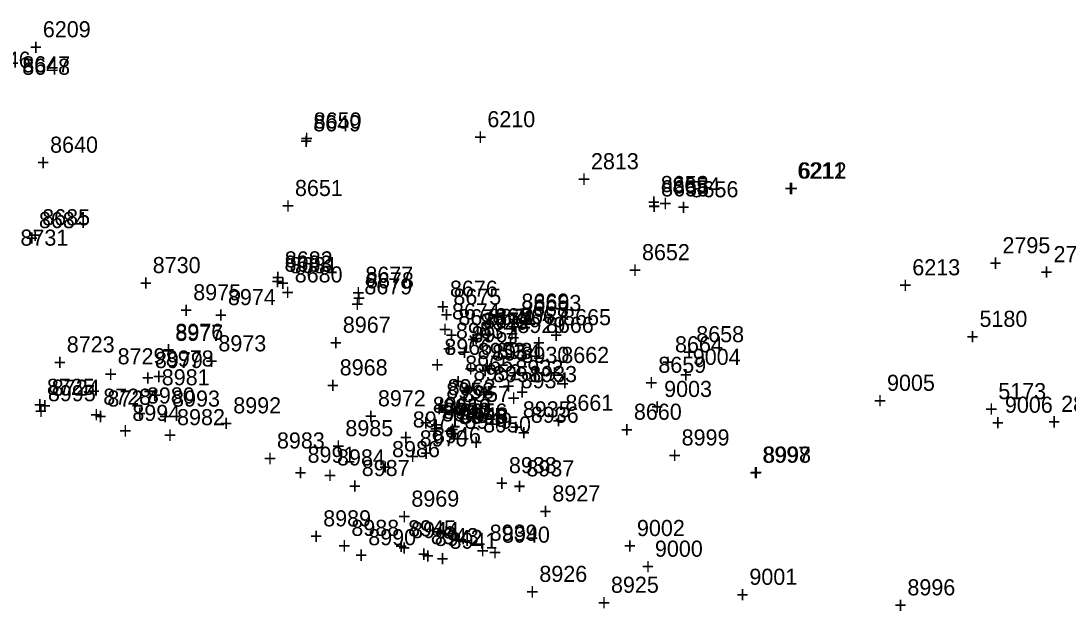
# Model space of a CAD drawing. Extents: x 1136220 to 1137808, y 528804 to 531215.
# Drawn here: x 1136624.6 to 1136787.3, y 529546.8 to 529638.4 of the extents above; entities that cross this region are included whole.
import ezdxf

# ---------------------------------------------------------------- set-up
doc = ezdxf.new("R2010")
doc.units = 0
for name, color, linetype in [('S_Buildings', 7, 'Continuous'), ('S_Buildings_Steps_Brick', 7, 'Continuous'), ('S_Curb_Type_3', 7, 'Continuous'), ('S_Drainage_Culvert_Top', 7, 'Continuous'), ('S_Fencing_BarbedWire', 7, 'Continuous'), ('S_Ground_Elevation', 7, 'Continuous'), ('S_Ground_LevelString', 7, 'Continuous'), ('S_Property_Garden', 7, 'Continuous'), ('S_Property_Walkways', 7, 'Continuous'), ('S_Roadway_Centerline', 7, 'Continuous'), ('S_Roadway_Drive_Gravel', 7, 'Continuous'), ('S_Roadway_Edge_Pavement', 7, 'Continuous'), ('S_Trees_Bush', 7, 'Continuous'), ('S_Trees_Bush_Line', 7, 'Continuous'), ('S_Trees_Conifer_NonPay', 7, 'Continuous'), ('S_Utilities_Gas_Gate', 7, 'Continuous'), ('S_Utilities_Pole_Joint', 7, 'Continuous'), ('S_Utilities_UG_Gas_Line', 7, 'Continuous'), ('S_Utilities_UG_Sanitary_MH', 7, 'Continuous')]:
    doc.layers.add(name, color=color, linetype=linetype)

msp = doc.modelspace()

# ---------------------------------------------------------------- texts
at = {"layer": 'S_Buildings'}
for s, p in [('8725', (1136628.65, 529580.36)), ('+', (1136626.59, 529577.61)), ('8991', (1136669.16, 529569.82)), ('+', (1136667.1, 529567.07))]:
    msp.add_text(s, height=2.5, dxfattribs=at).set_placement(p)
at = {"layer": 'S_Buildings_Steps_Brick'}
for s, p in [('8963', (1136692.21, 529589.07)), ('8964', (1136694.63, 529588.51)), ('+', (1136690.15, 529586.32)), ('+', (1136692.57, 529585.76)), ('8965', (1136693.66, 529583.96)), ('+', (1136691.6, 529581.21)), ('8958', (1136690.71, 529579.77)), ('8962', (1136690.94, 529580.31)), ('8957', (1136693.18, 529579.26)), ('+', (1136688.65, 529577.02)), ('+', (1136688.88, 529577.56)), ('8960', (1136690.17, 529576.63)), ('8959', (1136690.23, 529577.23)), ('+', (1136691.12, 529576.51)), ('8955', (1136692.61, 529575.84)), ('8956', (1136692.76, 529576.52)), ('+', (1136688.17, 529574.48)), ('+', (1136688.11, 529573.88)), ('+', (1136690.55, 529573.09)), ('+', (1136690.7, 529573.77))]:
    msp.add_text(s, height=2.5, dxfattribs=at).set_placement(p)
at = {"layer": 'S_Curb_Type_3'}
for s, p in [('8646', (1136618.69, 529631.15)), ('8647', (1136624.82, 529630.43)), ('8650', (1136670.11, 529621.71)), ('+', (1136668.04, 529618.96)), ('8653', (1136724.05, 529611.84)), ('8654', (1136725.84, 529611.61)), ('+', (1136721.99, 529609.09)), ('+', (1136723.78, 529608.86)), ('2795', (1136777.15, 529602.34)), ('2796', (1136785.08, 529600.96)), ('+', (1136775.08, 529599.59)), ('+', (1136783.02, 529598.21))]:
    msp.add_text(s, height=2.5, dxfattribs=at).set_placement(p)
at = {"layer": 'S_Drainage_Culvert_Top'}
for s, p in [('2806', (1136786.27, 529577.72)), ('+', (1136784.21, 529574.97))]:
    msp.add_text(s, height=2.5, dxfattribs=at).set_placement(p)
at = {"layer": 'S_Fencing_BarbedWire'}
for s, p in [('8995', (1136628.81, 529579.37)), ('+', (1136626.75, 529576.62)), ('8994', (1136641.93, 529576.31)), ('+', (1136639.87, 529573.56))]:
    msp.add_text(s, height=2.5, dxfattribs=at).set_placement(p)
at = {"layer": 'S_Ground_Elevation'}
for s, p in [('8684', (1136627.41, 529606.24)), ('8731', (1136624.54, 529603.52)), ('+', (1136625.35, 529603.49)), ('8730', (1136645.1, 529599.26)), ('8683', (1136665.57, 529599.48)), ('+', (1136643.04, 529596.51)), ('+', (1136663.51, 529596.73)), ('8975', (1136651.39, 529595.04)), ('8974', (1136656.78, 529594.29)), ('+', (1136649.33, 529592.29)), ('+', (1136654.72, 529591.54)), ('8928', (1136695.99, 529590.48)), ('8977', (1136648.61, 529588.74)), ('8976', (1136648.62, 529588.9)), ('8967', (1136674.64, 529590)), ('8929', (1136701.77, 529589.96)), ('8973', (1136655.3, 529587.11)), ('+', (1136693.93, 529587.73)), ('8723', (1136631.74, 529586.94)), ('+', (1136646.56, 529586.15)), ('+', (1136646.55, 529585.99)), ('+', (1136672.58, 529587.25)), ('8966', (1136690.42, 529586.56)), ('8953', (1136695.6, 529585.93)), ('8954', (1136697.83, 529585.67)), ('8931', (1136698.54, 529585.93)), ('+', (1136699.71, 529587.21)), ('8729', (1136639.64, 529585.1)), ('8979', (1136645.44, 529584.52)), ('8978', (1136647.13, 529584.76)), ('+', (1136653.24, 529584.36)), ('8930', (1136702.4, 529585.33)), ('9004', (1136729.02, 529585.01)), ('+', (1136629.68, 529584.19)), ('8968', (1136674.16, 529583.38)), ('+', (1136688.36, 529583.81)), ('+', (1136693.54, 529583.18)), ('8952', (1136694.94, 529582.6)), ('+', (1136695.77, 529582.92)), ('+', (1136696.48, 529583.18)), ('8951', (1136697.98, 529582.34)), ('+', (1136700.34, 529582.58)), ('8932', (1136701.46, 529583.27)), ('8933', (1136703.6, 529582.34)), ('+', (1136637.58, 529582.35)), ('+', (1136643.37, 529581.77)), ('+', (1136645.07, 529582.01)), ('8981', (1136646.5, 529581.84)), ('8934', (1136702.27, 529581.38)), ('+', (1136726.96, 529582.26)), ('9005', (1136759.21, 529580.99)), ('8724', (1136629.4, 529580.22)), ('8980', (1136644.19, 529579.02)), ('+', (1136672.1, 529580.63)), ('+', (1136692.88, 529579.85)), ('+', (1136695.92, 529579.59)), ('+', (1136699.4, 529580.52)), ('+', (1136701.54, 529579.59)), ('9003', (1136724.57, 529580.03)), ('8727', (1136638.06, 529578.54)), ('+', (1136644.44, 529579.09)), ('8972', (1136680.09, 529578.58)), ('8961', (1136688.62, 529577.55)), ('+', (1136700.21, 529578.63)), ('+', (1136757.15, 529578.24)), ('9006', (1136777.53, 529577.58)), ('+', (1136627.34, 529577.47)), ('+', (1136642.13, 529576.27)), ('8982', (1136648.88, 529575.65)), ('8935', (1136702.61, 529576.86)), ('8936', (1136703.86, 529576.03)), ('+', (1136722.51, 529577.28)), ('+', (1136636, 529575.79)), ('+', (1136678.03, 529575.83)), ('8971', (1136685.51, 529575.29)), ('+', (1136686.56, 529574.8)), ('8949', (1136693.54, 529575.1)), ('8950', (1136696.44, 529574.52)), ('+', (1136775.47, 529574.83)), ('+', (1136646.81, 529572.9)), ('8985', (1136675.03, 529573.94)), ('8946', (1136688.66, 529572.85)), ('+', (1136700.55, 529574.11)), ('+', (1136701.8, 529573.28)), ('8999', (1136727.29, 529572.5)), ('8983', (1136664.4, 529572.03)), ('+', (1136672.97, 529571.19)), ('+', (1136683.45, 529572.54)), ('8970', (1136686.59, 529572.35)), ('+', (1136691.47, 529572.35)), ('+', (1136694.38, 529571.77)), ('8984', (1136673.73, 529569.4)), ('8986', (1136682.29, 529570.69)), ('+', (1136684.52, 529569.6)), ('+', (1136686.6, 529570.1)), ('+', (1136725.23, 529569.75)), ('8997', (1136739.85, 529569.82)), ('8998', (1136739.96, 529569.83)), ('+', (1136662.34, 529569.28)), ('8987', (1136677.58, 529567.75)), ('+', (1136680.23, 529567.94)), ('8938', (1136700.45, 529568.2)), ('8937', (1136703.17, 529567.7)), ('+', (1136671.67, 529566.65)), ('+', (1136737.79, 529567.07)), ('+', (1136737.9, 529567.08)), ('+', (1136675.52, 529565)), ('+', (1136698.39, 529565.45)), ('+', (1136701.11, 529564.95)), ('8969', (1136685.29, 529563)), ('+', (1136683.23, 529560.25)), ('8988', (1136675.96, 529558.46)), ('8945', (1136684.79, 529558.39)), ('9002', (1136720.35, 529558.44)), ('8990', (1136678.59, 529557.01)), ('8942', (1136688.93, 529556.9)), ('8941', (1136691.22, 529556.47)), ('8939', (1136697.46, 529557.71)), ('8940', (1136699.38, 529557.41)), ('+', (1136673.9, 529555.71)), ('+', (1136682.72, 529555.64)), ('+', (1136695.39, 529554.96)), ('+', (1136718.28, 529555.69)), ('9000', (1136723.14, 529555.23)), ('+', (1136676.53, 529554.26)), ('+', (1136686.87, 529554.15)), ('+', (1136689.16, 529553.72)), ('+', (1136697.32, 529554.66)), ('+', (1136721.08, 529552.48)), ('9001', (1136737.82, 529550.87)), ('+', (1136735.76, 529548.12))]:
    msp.add_text(s, height=2.5, dxfattribs=at).set_placement(p)
at = {"layer": 'S_Ground_LevelString'}
for s, p in [('8678', (1136678.24, 529596.9)), ('+', (1136676.18, 529594.15)), ('8675', (1136691.82, 529594.35)), ('8668', (1136702.33, 529592.48)), ('+', (1136689.76, 529591.6)), ('8665', (1136708.88, 529591.17)), ('+', (1136700.27, 529589.73)), ('+', (1136706.82, 529588.42)), ('8664', (1136726.26, 529586.96)), ('+', (1136724.2, 529584.21))]:
    msp.add_text(s, height=2.5, dxfattribs=at).set_placement(p)
at = {"layer": 'S_Property_Garden'}
for s, p in [('8989', (1136671.59, 529559.94)), ('+', (1136669.53, 529557.19))]:
    msp.add_text(s, height=2.5, dxfattribs=at).set_placement(p)
at = {"layer": 'S_Property_Walkways'}
for s, p in [('8947', (1136690.01, 529576.24)), ('8948', (1136692.92, 529575.91)), ('+', (1136687.95, 529573.49)), ('+', (1136690.85, 529573.16)), ('8944', (1136685.25, 529558.13)), ('8943', (1136688.32, 529557.17)), ('+', (1136683.19, 529555.38)), ('+', (1136686.26, 529554.42))]:
    msp.add_text(s, height=2.5, dxfattribs=at).set_placement(p)
at = {"layer": 'S_Roadway_Centerline'}
for s, p in [('8640', (1136629.15, 529617.95)), ('+', (1136627.09, 529615.2)), ('8651', (1136667.2, 529611.23)), ('+', (1136665.14, 529608.48)), ('8652', (1136721.13, 529601.26)), ('+', (1136719.06, 529598.51)), ('5180', (1136773.58, 529590.92)), ('+', (1136771.51, 529588.17))]:
    msp.add_text(s, height=2.5, dxfattribs=at).set_placement(p)
at = {"layer": 'S_Roadway_Drive_Gravel'}
for s, p in [('8663', (1136704.27, 529593.38)), ('+', (1136702.21, 529590.63)), ('8662', (1136708.59, 529585.3)), ('8659', (1136723.67, 529583.78)), ('+', (1136706.53, 529582.55)), ('+', (1136721.61, 529581.03)), ('8661', (1136709.23, 529577.88)), ('8660', (1136719.87, 529576.49)), ('+', (1136707.17, 529575.13)), ('+', (1136717.81, 529573.74)), ('8927', (1136707.21, 529563.81)), ('+', (1136705.15, 529561.06)), ('8926', (1136705.18, 529551.32)), ('8925', (1136716.31, 529549.63)), ('+', (1136703.12, 529548.57)), ('+', (1136714.25, 529546.88))]:
    msp.add_text(s, height=2.5, dxfattribs=at).set_placement(p)
at = {"layer": 'S_Roadway_Edge_Pavement'}
for s, p in [('8648', (1136624.82, 529630.05)), ('8649', (1136670.04, 529621.27)), ('+', (1136667.98, 529618.52)), ('8655', (1136724.11, 529611.17)), ('8656', (1136728.68, 529611.03)), ('8685', (1136627.92, 529606.68)), ('+', (1136722.05, 529608.42)), ('+', (1136726.62, 529608.28)), ('+', (1136625.86, 529603.93)), ('8682', (1136665.62, 529600.14)), ('8681', (1136666.4, 529599.24)), ('+', (1136663.56, 529597.39)), ('8680', (1136667.16, 529597.81)), ('8677', (1136678.14, 529597.76)), ('+', (1136664.34, 529596.49)), ('8679', (1136677.99, 529595.96)), ('8676', (1136691.28, 529595.59)), ('+', (1136665.1, 529595.06)), ('+', (1136676.08, 529595.01)), ('8669', (1136702.4, 529593.59)), ('+', (1136675.92, 529593.21)), ('+', (1136689.22, 529592.84)), ('8674', (1136691.6, 529592.07)), ('8673', (1136692.6, 529591.16)), ('8672', (1136696.44, 529590.66)), ('8671', (1136697.22, 529591.22)), ('8670', (1136698.32, 529591.31)), ('+', (1136700.34, 529590.84)), ('8667', (1136702.02, 529591.38)), ('+', (1136689.54, 529589.32)), ('8666', (1136706.2, 529589.98)), ('+', (1136690.54, 529588.41)), ('+', (1136694.38, 529587.91)), ('+', (1136695.15, 529588.47)), ('+', (1136696.26, 529588.56)), ('+', (1136699.95, 529588.63)), ('8658', (1136729.56, 529588.53)), ('+', (1136704.14, 529587.23)), ('+', (1136727.5, 529585.78)), ('5173', (1136776.5, 529579.69)), ('+', (1136774.44, 529576.94))]:
    msp.add_text(s, height=2.5, dxfattribs=at).set_placement(p)
at = {"layer": 'S_Trees_Bush'}
for s, p in [('8728', (1136637.41, 529578.82)), ('8992', (1136657.61, 529577.48)), ('+', (1136635.35, 529576.07)), ('+', (1136655.55, 529574.73))]:
    msp.add_text(s, height=2.5, dxfattribs=at).set_placement(p)
at = {"layer": 'S_Trees_Bush_Line'}
for s, p in [('8996', (1136762.38, 529549.23)), ('+', (1136760.32, 529546.48))]:
    msp.add_text(s, height=2.5, dxfattribs=at).set_placement(p)
at = {"layer": 'S_Trees_Conifer_NonPay'}
for s, p in [('8993', (1136648.11, 529578.53)), ('+', (1136646.05, 529575.78))]:
    msp.add_text(s, height=2.5, dxfattribs=at).set_placement(p)
at = {"layer": 'S_Utilities_Gas_Gate'}
for s, p in [('6212', (1136745.48, 529613.94)), ('+', (1136743.42, 529611.19))]:
    msp.add_text(s, height=2.5, dxfattribs=at).set_placement(p)
at = {"layer": 'S_Utilities_Pole_Joint'}
for s, p in [('2813', (1136713.2, 529615.38)), ('+', (1136711.14, 529612.63))]:
    msp.add_text(s, height=2.5, dxfattribs=at).set_placement(p)
at = {"layer": 'S_Utilities_UG_Gas_Line'}
for s, p in [('6209', (1136628.02, 529635.87)), ('+', (1136625.96, 529633.12)), ('6210', (1136697.1, 529621.91)), ('+', (1136695.04, 529619.16)), ('6211', (1136745.28, 529613.94)), ('+', (1136743.22, 529611.19))]:
    msp.add_text(s, height=2.5, dxfattribs=at).set_placement(p)
at = {"layer": 'S_Utilities_UG_Sanitary_MH'}
for s, p in [('6213', (1136763.14, 529598.92)), ('+', (1136761.08, 529596.17))]:
    msp.add_text(s, height=2.5, dxfattribs=at).set_placement(p)

doc.saveas('drawing.dxf')
